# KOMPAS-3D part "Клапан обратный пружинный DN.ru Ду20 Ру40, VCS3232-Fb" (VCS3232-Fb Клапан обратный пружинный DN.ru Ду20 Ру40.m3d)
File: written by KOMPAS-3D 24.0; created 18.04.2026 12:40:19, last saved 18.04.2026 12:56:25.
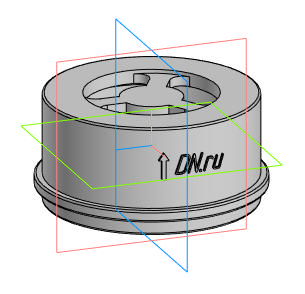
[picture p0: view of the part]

Document properties: Автор: 712; Полное имя файла: C:\Users\Пупс\Desktop\Работа\Работа\проверка\VCS3232-Fb WDVF Ду15-200 Ру40-25 Клапан обратный пружинный DN.ru\Ду20\VCS3232-Fb Клапан обратный пружинный DN.ru Ду20 Ру40.m3d

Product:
- Component: Пружина 1086-0796 ГОСТ 18793-80  | qty 1  | additional columns: 3953604318-4147491677-0; Деталь; Пользователь Windows; c; Шероховатость не задана; Да; Сталь 10  ГОСТ 1050-88; source file: Деталь.m3d
- Body: Тело 1  | qty 1
    Масса: 0.217807
- Part/product: Клапан обратный пружинный DN.ru Ду20 Ру40  | designation VCS3232-Fb
    Масса: 0.25
    Раздел спецификации: Прочие изделия
    Примечание: D100-03887
    additional columns: 071bd168-1a06-425c-849c-e99e84a96128; Деталь; 712; c; Шероховатость не задана; Да

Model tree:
1. Операция без истории:2

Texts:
  VCS3232-Fb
